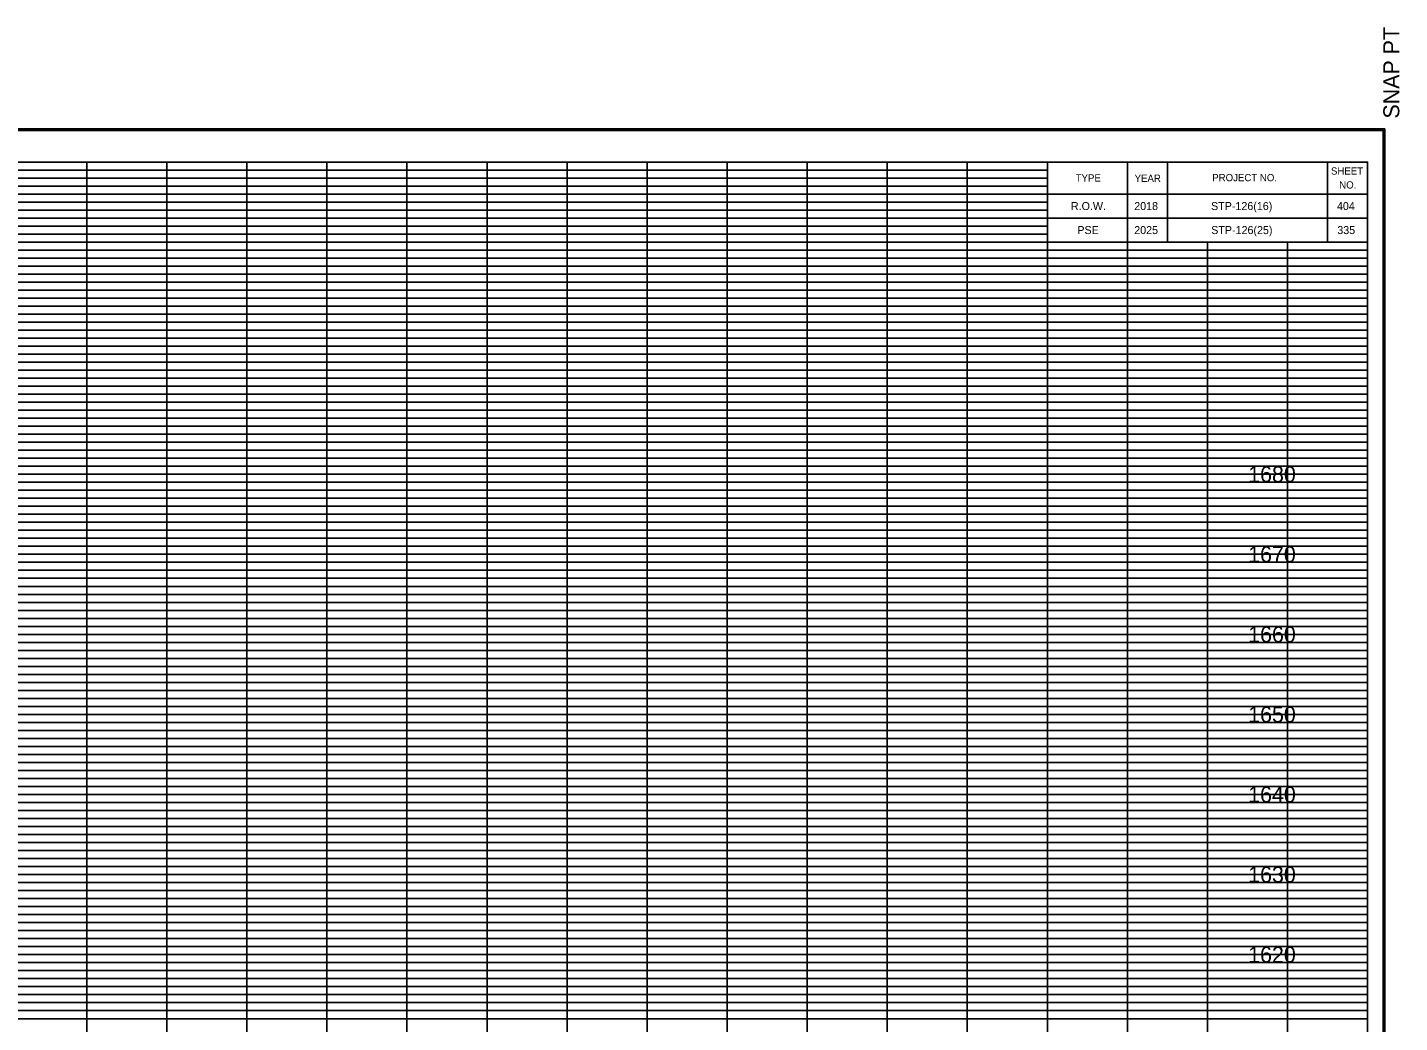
# Model space of a CAD drawing. Extents: x 980 to 1380, y 1248 to 3387.
# Drawn here: x 1152.6 to 1324, y 1912.5 to 2036.8 of the extents above; entities that cross this region are included whole.
import ezdxf

# ---------------------------------------------------------------- set-up
doc = ezdxf.new("R2010")
doc.units = 0
for name, color, linetype in [('DESIGN - SCRATCH - User 1', 7, 'Continuous'), ('DESIGN - SHEET - Corner Text', 7, 'Continuous'), ('DESIGN - SHEET - Light Grid', 7, 'Continuous'), ('DESIGN - SHEET - Linework', 7, 'Continuous'), ('DESIGN - SHEET - Plot Shape', 7, 'Continuous'), ('DESIGN - TYPICAL - Text', 7, 'Continuous')]:
    doc.layers.add(name, color=color, linetype=linetype)

# ---------------------------------------------------------------- blocks, each defined once
blk = doc.blocks.new('XSTSHT')
at = {"layer": 'DESIGN - SCRATCH - User 1'}
for p, q in [((28.5, 20.45), (28.5, 20.45)), ((29.24, 20.45), (29.24, 20.45)), ((30.49, 20.45), (30.49, 20.45)), ((31.74, 20.45), (31.74, 20.45)), ((28.5, 20.15), (28.5, 20.15)), ((29.24, 20.15), (29.24, 20.15)), ((30.49, 20.15), (30.49, 20.15)), ((31.74, 20.15), (31.74, 20.15))]:
    blk.add_line(p, q, dxfattribs=at)
at = {"layer": 'DESIGN - SHEET - Light Grid'}
for p, q in [((8, 20.9), (16, 20.9)), ((8, 20.8), (16, 20.8)), ((16, 20.9), (24, 20.9)), ((16, 20.8), (24, 20.8)), ((24, 20.9), (28, 20.9)), ((24, 20.8), (28, 20.8)), ((8, 20.7), (16, 20.7)), ((8, 20.6), (16, 20.6)), ((16, 20.7), (24, 20.7)), ((16, 20.6), (24, 20.6)), ((24, 20.7), (28, 20.7)), ((24, 20.6), (28, 20.6)), ((8, 20.5), (16, 20.5)), ((8, 20.4), (16, 20.4)), ((16, 20.5), (24, 20.5)), ((16, 20.4), (24, 20.4)), ((24, 20.5), (28, 20.5)), ((24, 20.4), (28, 20.4)), ((8, 20.3), (16, 20.3)), ((16, 20.3), (24, 20.3)), ((24, 20.3), (28, 20.3)), ((8, 20.2), (16, 20.2)), ((8, 20.1), (16, 20.1)), ((16, 20.2), (24, 20.2)), ((16, 20.1), (24, 20.1)), ((24, 20.2), (28, 20.2)), ((24, 20.1), (28, 20.1)), ((8, 19.9), (16, 19.9)), ((16, 19.9), (24, 19.9)), ((24, 19.9), (32, 19.9)), ((8, 19.8), (16, 19.8)), ((16, 19.8), (24, 19.8)), ((24, 19.8), (32, 19.8)), ((8, 19.7), (16, 19.7)), ((8, 19.6), (16, 19.6)), ((16, 19.7), (24, 19.7)), ((16, 19.6), (24, 19.6)), ((24, 19.7), (32, 19.7)), ((24, 19.6), (32, 19.6)), ((8, 19.5), (16, 19.5)), ((8, 19.4), (16, 19.4)), ((16, 19.5), (24, 19.5)), ((16, 19.4), (24, 19.4)), ((24, 19.5), (32, 19.5)), ((24, 19.4), (32, 19.4)), ((8, 19.3), (16, 19.3)), ((8, 19.2), (16, 19.2)), ((16, 19.3), (24, 19.3)), ((16, 19.2), (24, 19.2)), ((24, 19.3), (32, 19.3)), ((24, 19.2), (32, 19.2)), ((8, 19.1), (16, 19.1)), ((16, 19.1), (24, 19.1)), ((24, 19.1), (32, 19.1)), ((8, 18.9), (16, 18.9)), ((16, 18.9), (24, 18.9)), ((24, 18.9), (32, 18.9)), ((8, 18.8), (16, 18.8)), ((8, 18.7), (16, 18.7)), ((16, 18.8), (24, 18.8)), ((16, 18.7), (24, 18.7)), ((24, 18.8), (32, 18.8)), ((24, 18.7), (32, 18.7)), ((8, 18.6), (16, 18.6)), ((16, 18.6), (24, 18.6)), ((24, 18.6), (32, 18.6)), ((8, 18.5), (16, 18.5)), ((8, 18.4), (16, 18.4)), ((16, 18.5), (24, 18.5)), ((16, 18.4), (24, 18.4)), ((24, 18.5), (32, 18.5)), ((24, 18.4), (32, 18.4)), ((8, 18.3), (16, 18.3)), ((8, 18.2), (16, 18.2)), ((16, 18.3), (24, 18.3)), ((16, 18.2), (24, 18.2)), ((24, 18.3), (32, 18.3)), ((24, 18.2), (32, 18.2)), ((8, 18.1), (16, 18.1)), ((16, 18.1), (24, 18.1)), ((24, 18.1), (32, 18.1)), ((8, 17.9), (16, 17.9)), ((16, 17.9), (24, 17.9)), ((24, 17.9), (32, 17.9)), ((8, 17.8), (16, 17.8)), ((8, 17.7), (16, 17.7)), ((16, 17.8), (24, 17.8)), ((16, 17.7), (24, 17.7)), ((24, 17.8), (32, 17.8)), ((24, 17.7), (32, 17.7)), ((8, 17.6), (16, 17.6)), ((8, 17.5), (16, 17.5)), ((16, 17.6), (24, 17.6)), ((16, 17.5), (24, 17.5)), ((24, 17.6), (32, 17.6)), ((24, 17.5), (32, 17.5)), ((8, 17.4), (16, 17.4)), ((16, 17.4), (24, 17.4)), ((24, 17.4), (32, 17.4)), ((8, 17.3), (16, 17.3)), ((8, 17.2), (16, 17.2)), ((16, 17.3), (24, 17.3)), ((16, 17.2), (24, 17.2)), ((24, 17.3), (32, 17.3)), ((24, 17.2), (32, 17.2)), ((8, 17.1), (16, 17.1)), ((16, 17.1), (24, 17.1)), ((24, 17.1), (32, 17.1)), ((8, 16.9), (16, 16.9)), ((8, 16.8), (16, 16.8)), ((16, 16.9), (24, 16.9)), ((16, 16.8), (24, 16.8)), ((24, 16.9), (32, 16.9)), ((24, 16.8), (32, 16.8)), ((8, 16.7), (16, 16.7)), ((16, 16.7), (24, 16.7)), ((24, 16.7), (32, 16.7)), ((8, 16.6), (16, 16.6)), ((8, 16.5), (16, 16.5)), ((16, 16.6), (24, 16.6)), ((16, 16.5), (24, 16.5)), ((24, 16.6), (32, 16.6)), ((24, 16.5), (32, 16.5)), ((8, 16.4), (16, 16.4)), ((8, 16.3), (16, 16.3)), ((16, 16.4), (24, 16.4)), ((16, 16.3), (24, 16.3)), ((24, 16.4), (32, 16.4)), ((24, 16.3), (32, 16.3)), ((8, 16.2), (16, 16.2)), ((16, 16.2), (24, 16.2)), ((24, 16.2), (32, 16.2)), ((8, 16.1), (16, 16.1)), ((16, 16.1), (24, 16.1)), ((24, 16.1), (32, 16.1)), ((8, 15.9), (16, 15.9)), ((8, 15.8), (16, 15.8)), ((16, 15.9), (24, 15.9)), ((16, 15.8), (24, 15.8)), ((24, 15.9), (32, 15.9)), ((24, 15.8), (32, 15.8)), ((8, 15.7), (16, 15.7)), ((8, 15.6), (16, 15.6)), ((16, 15.7), (24, 15.7)), ((16, 15.6), (24, 15.6)), ((24, 15.7), (32, 15.7)), ((24, 15.6), (32, 15.6)), ((8, 15.5), (16, 15.5)), ((16, 15.5), (24, 15.5)), ((24, 15.5), (32, 15.5)), ((8, 15.4), (16, 15.4)), ((8, 15.3), (16, 15.3)), ((16, 15.4), (24, 15.4)), ((16, 15.3), (24, 15.3)), ((24, 15.4), (32, 15.4)), ((24, 15.3), (32, 15.3)), ((8, 15.2), (16, 15.2)), ((8, 15.1), (16, 15.1)), ((16, 15.2), (24, 15.2)), ((16, 15.1), (24, 15.1)), ((24, 15.2), (32, 15.2)), ((24, 15.1), (32, 15.1)), ((8, 14.9), (16, 14.9)), ((8, 14.8), (16, 14.8)), ((16, 14.9), (24, 14.9)), ((16, 14.8), (24, 14.8)), ((24, 14.9), (32, 14.9)), ((24, 14.8), (32, 14.8)), ((8, 14.7), (16, 14.7)), ((8, 14.6), (16, 14.6)), ((16, 14.7), (24, 14.7)), ((16, 14.6), (24, 14.6)), ((24, 14.7), (32, 14.7)), ((24, 14.6), (32, 14.6)), ((8, 14.5), (16, 14.5)), ((8, 14.4), (16, 14.4)), ((16, 14.5), (24, 14.5)), ((16, 14.4), (24, 14.4)), ((24, 14.5), (32, 14.5)), ((24, 14.4), (32, 14.4)), ((8, 14.3), (16, 14.3)), ((16, 14.3), (24, 14.3)), ((24, 14.3), (32, 14.3)), ((8, 14.2), (16, 14.2)), ((8, 14.1), (16, 14.1)), ((16, 14.2), (24, 14.2)), ((16, 14.1), (24, 14.1)), ((24, 14.2), (32, 14.2)), ((24, 14.1), (32, 14.1)), ((8, 13.9), (16, 13.9)), ((16, 13.9), (24, 13.9)), ((24, 13.9), (32, 13.9)), ((8, 13.8), (16, 13.8)), ((16, 13.8), (24, 13.8)), ((24, 13.8), (32, 13.8)), ((8, 13.7), (16, 13.7)), ((8, 13.6), (16, 13.6)), ((16, 13.7), (24, 13.7)), ((16, 13.6), (24, 13.6)), ((24, 13.7), (32, 13.7)), ((24, 13.6), (32, 13.6)), ((8, 13.5), (16, 13.5)), ((8, 13.4), (16, 13.4)), ((16, 13.5), (24, 13.5)), ((16, 13.4), (24, 13.4)), ((24, 13.5), (32, 13.5)), ((24, 13.4), (32, 13.4)), ((8, 13.3), (16, 13.3)), ((8, 13.2), (16, 13.2)), ((16, 13.3), (24, 13.3)), ((16, 13.2), (24, 13.2)), ((24, 13.3), (32, 13.3)), ((24, 13.2), (32, 13.2)), ((8, 13.1), (16, 13.1)), ((16, 13.1), (24, 13.1)), ((24, 13.1), (32, 13.1)), ((8, 12.9), (16, 12.9)), ((16, 12.9), (24, 12.9)), ((24, 12.9), (32, 12.9)), ((8, 12.8), (16, 12.8)), ((8, 12.7), (16, 12.7)), ((16, 12.8), (24, 12.8)), ((16, 12.7), (24, 12.7)), ((24, 12.8), (32, 12.8)), ((24, 12.7), (32, 12.7)), ((8, 12.6), (16, 12.6)), ((16, 12.6), (24, 12.6)), ((24, 12.6), (32, 12.6)), ((8, 12.5), (16, 12.5)), ((8, 12.4), (16, 12.4)), ((16, 12.5), (24, 12.5)), ((16, 12.4), (24, 12.4)), ((24, 12.5), (32, 12.5)), ((24, 12.4), (32, 12.4)), ((8, 12.3), (16, 12.3)), ((8, 12.2), (16, 12.2)), ((16, 12.3), (24, 12.3)), ((16, 12.2), (24, 12.2)), ((24, 12.3), (32, 12.3)), ((24, 12.2), (32, 12.2)), ((8, 12.1), (16, 12.1)), ((16, 12.1), (24, 12.1)), ((24, 12.1), (32, 12.1)), ((8, 11.9), (16, 11.9)), ((16, 11.9), (24, 11.9)), ((24, 11.9), (32, 11.9)), ((8, 11.8), (16, 11.8)), ((8, 11.7), (16, 11.7)), ((16, 11.8), (24, 11.8)), ((16, 11.7), (24, 11.7)), ((24, 11.8), (32, 11.8)), ((24, 11.7), (32, 11.7)), ((8, 11.6), (16, 11.6)), ((8, 11.5), (16, 11.5)), ((16, 11.6), (24, 11.6)), ((16, 11.5), (24, 11.5)), ((24, 11.6), (32, 11.6)), ((24, 11.5), (32, 11.5)), ((8, 11.4), (16, 11.4)), ((16, 11.4), (24, 11.4)), ((24, 11.4), (32, 11.4)), ((8, 11.3), (16, 11.3)), ((8, 11.2), (16, 11.2)), ((16, 11.3), (24, 11.3)), ((16, 11.2), (24, 11.2)), ((24, 11.3), (32, 11.3)), ((24, 11.2), (32, 11.2)), ((8, 11.1), (16, 11.1)), ((16, 11.1), (24, 11.1)), ((24, 11.1), (32, 11.1)), ((8, 10.9), (16, 10.9)), ((8, 10.8), (16, 10.8)), ((16, 10.9), (24, 10.9)), ((16, 10.8), (24, 10.8)), ((24, 10.9), (32, 10.9)), ((24, 10.8), (32, 10.8)), ((8, 10.7), (16, 10.7)), ((16, 10.7), (24, 10.7)), ((24, 10.7), (32, 10.7)), ((8, 10.6), (16, 10.6)), ((8, 10.5), (16, 10.5)), ((16, 10.6), (24, 10.6)), ((16, 10.5), (24, 10.5)), ((24, 10.6), (32, 10.6)), ((24, 10.5), (32, 10.5)), ((8, 10.4), (16, 10.4)), ((8, 10.3), (16, 10.3)), ((16, 10.4), (24, 10.4)), ((16, 10.3), (24, 10.3)), ((24, 10.4), (32, 10.4)), ((24, 10.3), (32, 10.3))]:
    blk.add_line(p, q, dxfattribs=at)
at = {"layer": 'DESIGN - SHEET - Linework'}
for p, q in [((-1.823, 21.414), (32.217, 21.414)), ((32.217, 21.414), (32.217, -0.414)), ((16, 0), (16, 21)), ((17, 0), (17, 21)), ((18, 0), (18, 21)), ((19, 0), (19, 21)), ((20, 0), (20, 21)), ((21, 0), (21, 21)), ((22, 0), (22, 21)), ((23, 0), (23, 21)), ((24, 0), (24, 21)), ((25, 0), (25, 21)), ((26, 0), (26, 21)), ((27, 0), (27, 21)), ((0, 20), (28, 20)), ((28, 0), (28, 20)), ((29, 0), (29, 20)), ((30, 0), (30, 20)), ((31, 0), (31, 20)), ((0, 19), (32, 19)), ((0, 18), (32, 18)), ((0, 17), (32, 17)), ((0, 16), (32, 16)), ((0, 15), (32, 15)), ((0, 14), (32, 14)), ((0, 13), (32, 13)), ((0, 12), (32, 12)), ((0, 11), (32, 11))]:
    blk.add_line(p, q, dxfattribs=at)
for points in [[(0, 21), (0, 0), (32, 0), (32, 21), (0, 21)], [(28, 21), (28, 20), (32, 20), (32, 21), (31.5, 21), (31.5, 20), (29.5, 20), (29.5, 21), (29, 21), (29, 20), (32, 20), (28, 20), (28, 20.3), (32, 20.3), (32, 20.6), (28, 20.6)]]:
    blk.add_lwpolyline(points, dxfattribs=at)
at = {"layer": 'DESIGN - SHEET - Plot Shape'}
for points in [[(-1.803, 21.394), (32.197, 21.394), (32.197, -0.394), (-1.803, -0.394)], [(-0.85, 21), (32, 21), (32, -0.25), (-0.85, -0.25)]]:
    blk.add_lwpolyline(points, close=True, dxfattribs=at)
at = {"layer": 'DESIGN - SHEET - Corner Text'}
blk.add_text('  SNAP PT', height=0.2, rotation=90, dxfattribs=at).set_placement((32.397, 21.394))
for s, p in [('SHEET', (31.543, 20.843)), ('TYPE', (28.354, 20.756)), ('YEAR', (29.09, 20.752)), ('PROJECT NO.', (30.06, 20.76)), ('NO.', (31.646, 20.669))]:
    blk.add_text(s, height=0.09, dxfattribs=at).set_placement(p)

msp = doc.modelspace()

# ---------------------------------------------------------------- linework, layer by layer
at = {"layer": 'DESIGN - SHEET - Plot Shape'}
msp.add_lwpolyline([(991.5, 1807.5), (1320, 1807.5), (1320, 2020), (991.5, 2020)], close=True, dxfattribs=at)

# ---------------------------------------------------------------- block references
at = {"layer": 'DESIGN - TYPICAL - Text', "xscale": 10, "yscale": 10}
msp.add_blockref('XSTSHT', (1000, 1810), dxfattribs=at)

# ---------------------------------------------------------------- texts
at = {"layer": 'DESIGN - SHEET - Corner Text'}
for s, p in [('R.O.W.', (1282.94, 2014)), ('2018', (1290.85, 2014)), ('STP-126(16)', (1300.45, 2014)), ('404', (1316.18, 2014)), ('PSE', (1283.75, 2011)), ('2025', (1290.85, 2011)), ('STP-126(25)', (1300.47, 2011)), ('335', (1316.22, 2011))]:
    msp.add_text(s, height=1, dxfattribs=at).set_placement(p)
at = {"layer": 'DESIGN - TYPICAL - Text'}
for s, p in [('     1680     ', (1301.37, 1980)), ('     1670     ', (1301.37, 1970)), ('     1660     ', (1301.37, 1960)), ('     1650     ', (1301.37, 1950)), ('     1640     ', (1301.37, 1940)), ('     1630     ', (1301.37, 1930)), ('     1620     ', (1301.37, 1920))]:
    msp.add_text(s, height=2, dxfattribs=at).set_placement(p)

doc.saveas('drawing.dxf')
